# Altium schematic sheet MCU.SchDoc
size A4; Revision: A.1(PCB.SCH)
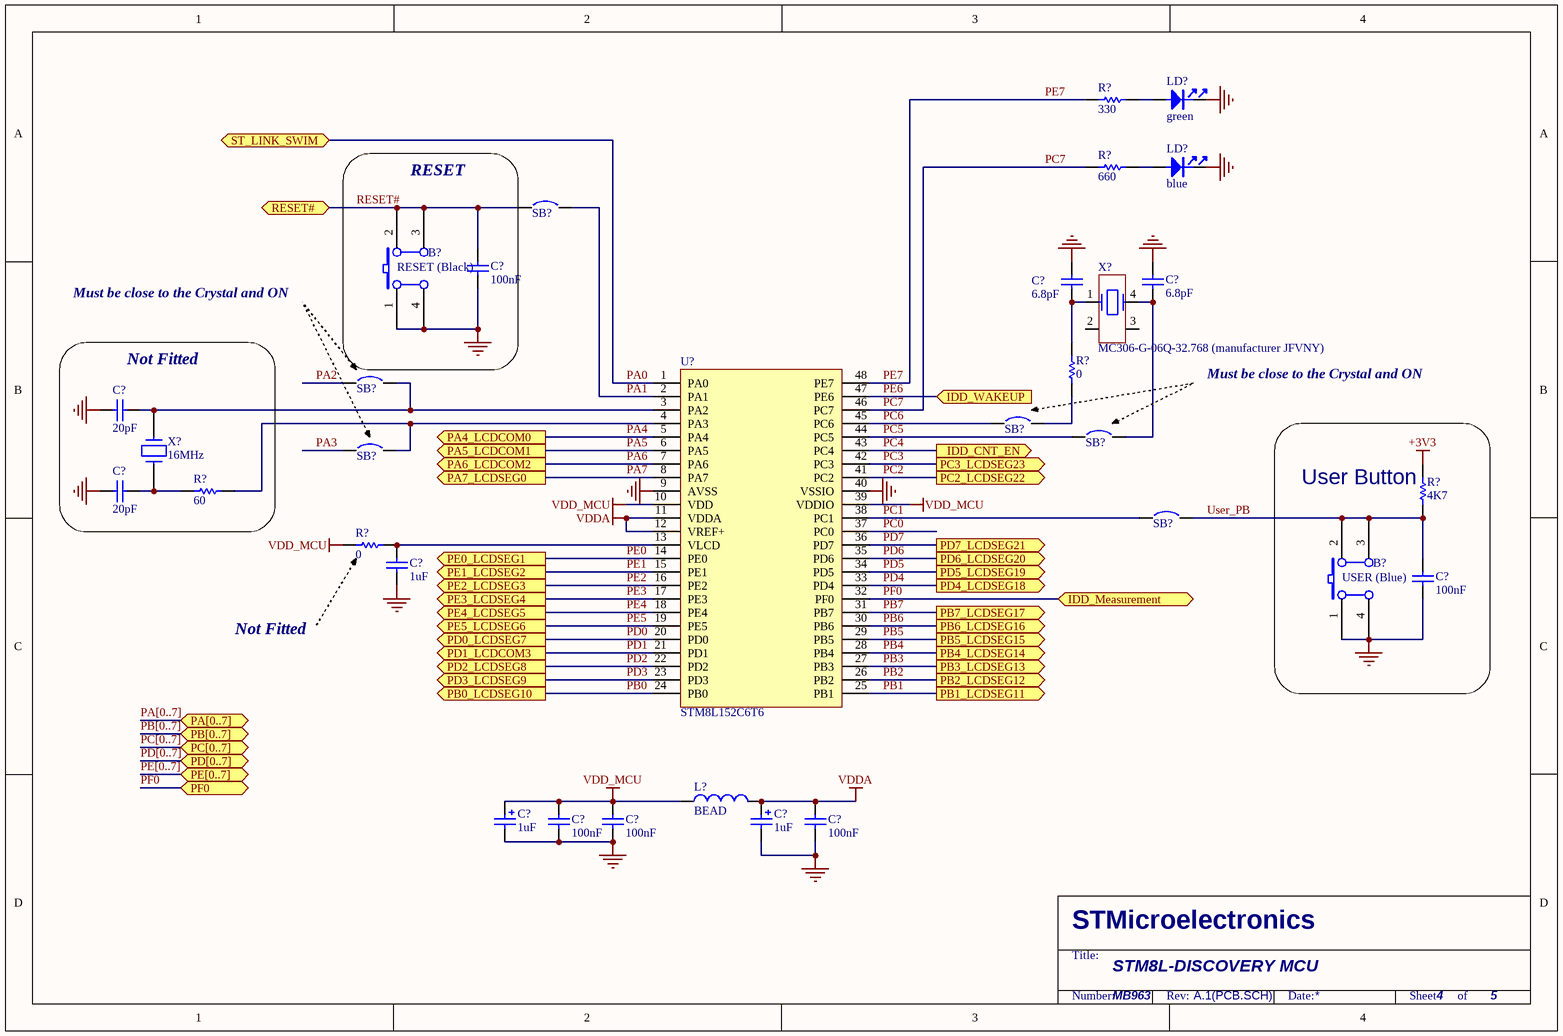
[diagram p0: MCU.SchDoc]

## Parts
(Parts that share a designator on the sheet are numbered #1, #2 ... from top to bottom, then left to right.)
B?#1  RESET (Black)  [PB10]
B?#2  USER (Blue)  [PB10]
C?#1  100nF  [0402C]
C?#2  6.8pF  [0402C]
C?#3  6.8pF  [0402C]
C?#4  20pF  [0402C]
C?#5  20pF  [0402C]
C?#6  1uF  [0402C]
C?#7  100nF  [0402C]
C?#8  1uF  [0603C]
C?#9  1uF  [0603C]
C?#10  100nF  [0402C]
C?#11  100nF  [0402C]
C?#12  100nF  [0402C]
L?  BEAD  [0603L]
LD?#1  green  [LED0603]
LD?#2  blue  [LED0603]
R?#1  330  [0402R]
R?#2  660  [0402R]
R?#3  0  [0402R]
R?#4  60  [0402R]
R?#5  4K7  [0402R]
R?#6  0  [0402R]
SB?#1  Circuit Breaker  [JP2_SMD]  (value not drawn)
SB?#2  Circuit Breaker  [JP2_SMD]  (value not drawn)
SB?#3  Circuit Breaker  [JP2_SMD]  (value not drawn)
SB?#4  Circuit Breaker  [JP2_SMD]  (value not drawn)
SB?#5  Circuit Breaker  [JP2_SMD]  (value not drawn)
SB?#6  Circuit Breaker  [JP2_SMD]  (value not drawn)
U?  STM8L152C6T6  [LQFP48]
X?#1  MC306-G-06Q-32.768 (manufacturer JFVNY)  [SM8]
X?#2  16MHz  [XTAL1]

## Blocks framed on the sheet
RESET: B?#1 C?#1
Not Fitted: C?#4 C?#5 R?#4 X?#2
User Button: B?#2 C?#7 R?#5

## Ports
IDD_CNT_EN (out), IDD_Measurement (bidir), IDD_WAKEUP (in), PA4_LCDCOM0 (out), PA5_LCDCOM1 (out), PA6_LCDCOM2 (out), PA7_LCDSEG0 (out), PA[0..7] (bidir), PB0_LCDSEG10 (out), PB1_LCDSEG11 (out), PB2_LCDSEG12 (out), PB3_LCDSEG13 (out), PB4_LCDSEG14 (out), PB5_LCDSEG15 (out), PB6_LCDSEG16 (out), PB7_LCDSEG17 (out), PB[0..7] (bidir), PC2_LCDSEG22 (out), PC3_LCDSEG23 (out), PC[0..7] (bidir), PD0_LCDSEG7 (out), PD1_LCDCOM3 (out), PD2_LCDSEG8 (out), PD3_LCDSEG9 (out), PD4_LCDSEG18 (out), PD5_LCDSEG19 (out), PD6_LCDSEG20 (out), PD7_LCDSEG21 (out), PD[0..7] (bidir), PE0_LCDSEG1 (out), PE1_LCDSEG2 (out), PE2_LCDSEG3 (out), PE3_LCDSEG4 (out), PE4_LCDSEG5 (out), PE5_LCDSEG6 (out), PE[0..7] (bidir), PF0 (bidir), RESET# (bidir), ST_LINK_SWIM (bidir)

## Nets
+3V3: R?#5.2
GND: B?#1.1(A0) B?#1.4(A1) B?#2.1(A0) B?#2.4(A1) C?#1.1 C?#2.2 C?#3.2 C?#4.1 C?#5.1 C?#6.1 C?#7.1 C?#8.2 C?#9.2 C?#10.2 C?#11.1 C?#12.1 LD?#1.2 LD?#2.2 U?.9(AVSS) U?.40(VSSIO)
VDD_MCU: C?#8.1 C?#11.2 C?#12.2 L?.1 R?#6.1 U?.10(VDD) U?.39(VDDIO)
VDDA: C?#9.1 C?#10.1 L?.2 U?.11(VDDA) U?.12(VREF+)
PA0: U?.1(PA0) ; port ST_LINK_SWIM
PA1: SB?#1.2 U?.2(PA1)
PA2: SB?#2.1
PA3: SB?#5.1
PA4: U?.5(PA4) ; port PA4_LCDCOM0
PA5: U?.6(PA5) ; port PA5_LCDCOM1
PA6: U?.7(PA6) ; port PA6_LCDCOM2
PA7: U?.8(PA7) ; port PA7_LCDSEG0
PB0: U?.24(PB0) ; port PB0_LCDSEG10
PB1: U?.25(PB1) ; port PB1_LCDSEG11
PB2: U?.26(PB2) ; port PB2_LCDSEG12
PB3: U?.27(PB3) ; port PB3_LCDSEG13
PB4: U?.28(PB4) ; port PB4_LCDSEG14
PB5: U?.29(PB5) ; port PB5_LCDSEG15
PB6: U?.30(PB6) ; port PB6_LCDSEG16
PB7: U?.31(PB7) ; port PB7_LCDSEG17
PC0: U?.37(PC0)
PC1: SB?#6.1 U?.38(PC1)
PC2: U?.41(PC2) ; port PC2_LCDSEG22
PC3: U?.42(PC3) ; port PC3_LCDSEG23
PC4: U?.43(PC4) ; port IDD_CNT_EN
PC5: SB?#4.1 U?.44(PC5)
PC6: SB?#3.1 U?.45(PC6)
PC7: R?#2.1 U?.46(PC7)
PD0: U?.20(PD0) ; port PD0_LCDSEG7
PD1: U?.21(PD1) ; port PD1_LCDCOM3
PD2: U?.22(PD2) ; port PD2_LCDSEG8
PD3: U?.23(PD3) ; port PD3_LCDSEG9
PD4: U?.33(PD4) ; port PD4_LCDSEG18
PD5: U?.34(PD5) ; port PD5_LCDSEG19
PD6: U?.35(PD6) ; port PD6_LCDSEG20
PD7: U?.36(PD7) ; port PD7_LCDSEG21
PE0: U?.14(PE0) ; port PE0_LCDSEG1
PE1: U?.15(PE1) ; port PE1_LCDSEG2
PE2: U?.16(PE2) ; port PE2_LCDSEG3
PE3: U?.17(PE3) ; port PE3_LCDSEG4
PE4: U?.18(PE4) ; port PE4_LCDSEG5
PE5: U?.19(PE5) ; port PE5_LCDSEG6
PE6: U?.47(PE6) ; port IDD_WAKEUP
PE7: R?#1.1 U?.48(PE7)
PF0: U?.32(PF0) ; port PF0, port IDD_Measurement
RESET#: B?#1.2(B0) B?#1.3(B1) C?#1.2 SB?#1.1 ; port RESET#
User_PB: B?#2.2(B0) B?#2.3(B1) C?#7.2 R?#5.1 SB?#6.2
NetC?#2_1: C?#2.1 R?#3.2 X?#1.1
NetC?#3_1: C?#3.1 SB?#4.2 X?#1.4
NetC?#4_2: C?#4.2 SB?#2.2 U?.3(PA2) X?#2.2
NetC?#5_2: C?#5.2 R?#4.1 X?#2.1
NetC?#6_2: C?#6.2 R?#6.2 U?.13(VLCD)
NetLD?#1_1: LD?#1.1 R?#1.2
NetLD?#2_1: LD?#2.1 R?#2.2
NetR?#3_1: R?#3.1 SB?#3.2
NetR?#4_2: R?#4.2 SB?#5.2 U?.4(PA3)

Not connected (* = marked no-connect by the designer): X?#1 2 3

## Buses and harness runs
bus PA[0..7] = port PA[0..7]
bus PB[0..7] = port PB[0..7]
bus PC[0..7] = port PC[0..7]
bus PD[0..7] = port PD[0..7]
bus PE[0..7] = port PE[0..7]

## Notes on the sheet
- Must be close to the Crystal and ON
- Not Fitted
- STM8L-DISCOVERY MCU
- MB963
- 4
- 5

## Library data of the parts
B?#1 B?#2 = SW PUSHBUTTON: SE PUSHBUTTON
C?#1-C?#3 C?#5-C?#7 C?#10-C?#12 = Cap: Capacitor
C?#4 = Cap: Capacitor; Fitted: NO
C?#8 C?#9 = Cap Pol1: Polarized Capacitor (Radial)
L? = Inductor: Value: 100uH
LD?#1 LD?#2 = PHOTO
R?#1 R?#2 R?#5 = res1: Resistor
R?#3 R?#4 R?#6 = res1: Resistor; Fitted: NO
SB?#1-SB?#6 = Circuit Breaker: Solder: YES
U? = STM8L2xx_QFP48: Provided: ST
X?#1 = MC306
X?#2 = CRYSTAL: Fitted: NO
